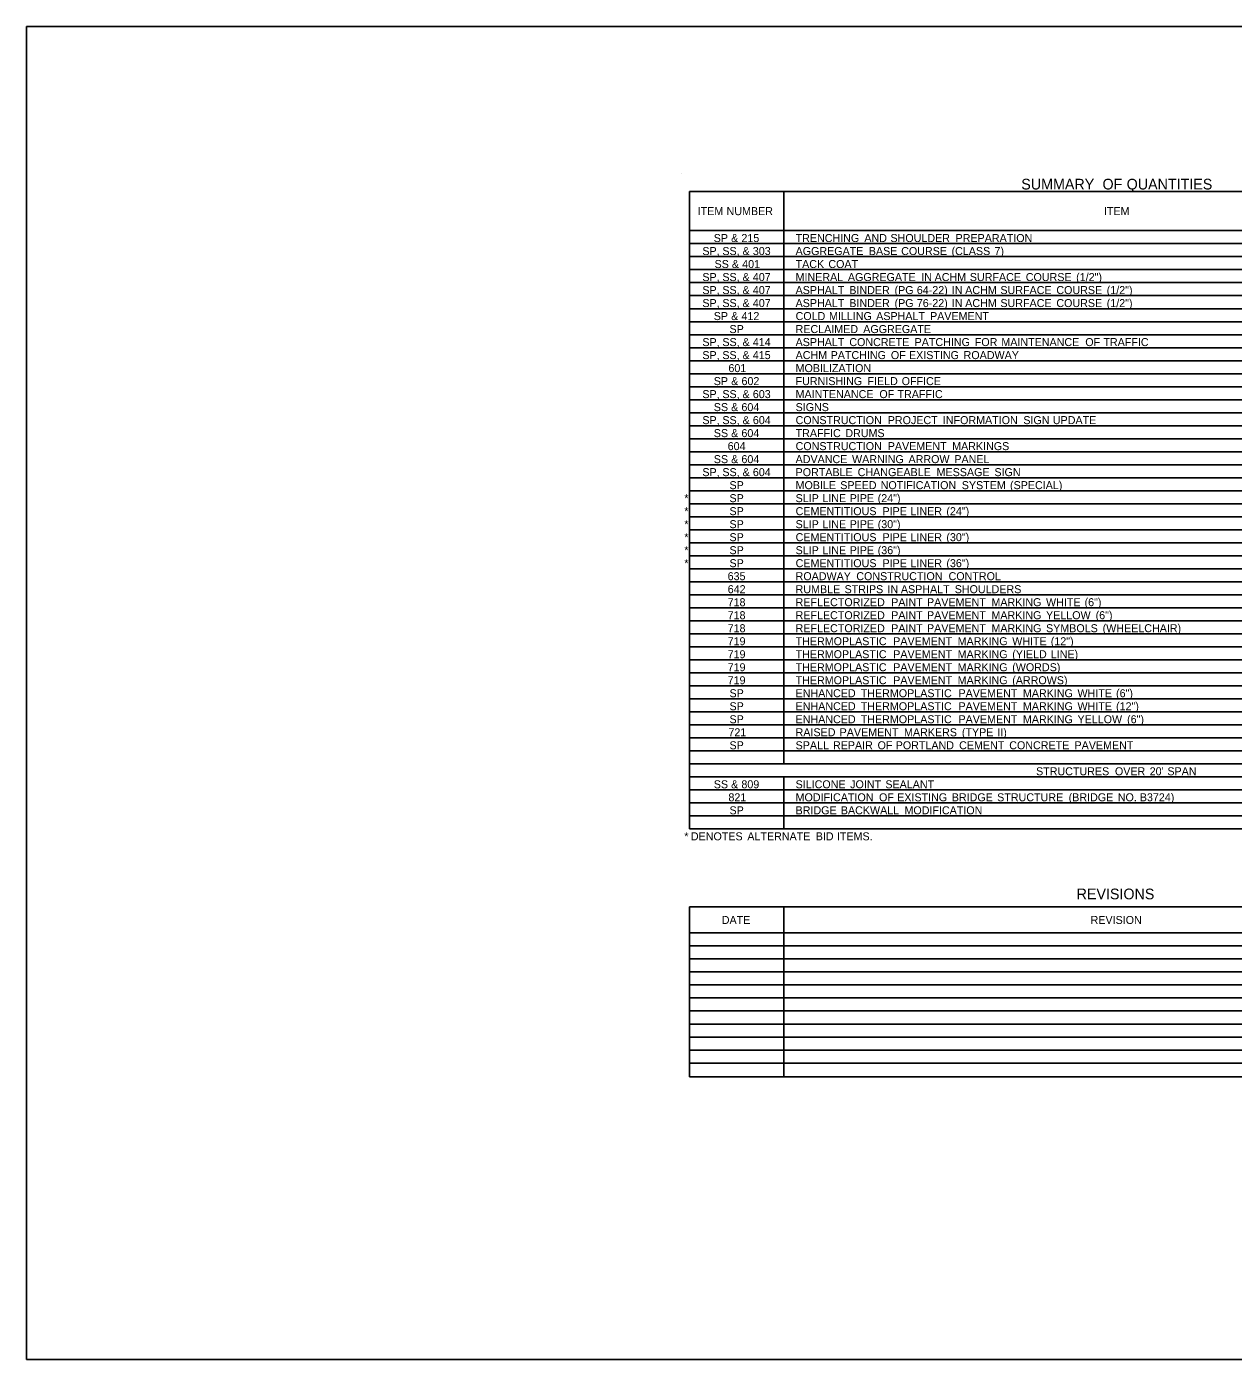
# Model space of a CAD drawing. Extents: x 2261867 to 2275370, y -3124789 to -3122260.
# Drawn here: x 2273745 to 2274649, y -3124789 to -3123790 of the extents above; entities that cross this region are included whole.
import ezdxf

# ---------------------------------------------------------------- set-up
doc = ezdxf.new("R2010")
doc.units = 0
for name, color, linetype in [('Default', 7, 'Continuous'), ('DSN_DRFT_DNC', 7, 'Continuous'), ('DSN_DRFT_Named-Boundary', 7, 'Continuous')]:
    doc.layers.add(name, color=color, linetype=linetype)

msp = doc.modelspace()

# ---------------------------------------------------------------- linework, layer by layer
at = {"layer": 'Default'}
for p, q in [((2274241.54, -3123913.99), (2274312.22, -3123913.99)), ((2274241.54, -3123913.99), (2274910.87, -3123913.99)), ((2274241.54, -3124391.74), (2274241.54, -3123913.99)), ((2274241.54, -3124391.74), (2274241.54, -3123913.99)), ((2274312.22, -3124342.99), (2274312.22, -3123913.99)), ((2274241.54, -3123943.24), (2274910.87, -3123943.24)), ((2274241.54, -3123943.24), (2274910.87, -3123943.24)), ((2274312.22, -3124342.99), (2274312.22, -3123943.24)), ((2274241.54, -3123952.99), (2274910.87, -3123952.99)), ((2274241.54, -3123962.74), (2274910.87, -3123962.74)), ((2274241.54, -3123972.49), (2274910.87, -3123972.49)), ((2274241.54, -3123982.24), (2274910.87, -3123982.24)), ((2274241.54, -3123991.99), (2274910.87, -3123991.99)), ((2274241.54, -3124001.74), (2274910.87, -3124001.74)), ((2274241.54, -3124011.49), (2274910.87, -3124011.49)), ((2274241.54, -3124021.24), (2274910.87, -3124021.24)), ((2274241.54, -3124030.99), (2274910.87, -3124030.99)), ((2274241.54, -3124040.74), (2274910.87, -3124040.74)), ((2274241.54, -3124050.49), (2274910.87, -3124050.49)), ((2274241.54, -3124060.24), (2274910.87, -3124060.24)), ((2274241.54, -3124069.99), (2274910.87, -3124069.99)), ((2274241.54, -3124079.74), (2274910.87, -3124079.74)), ((2274241.54, -3124089.49), (2274910.87, -3124089.49)), ((2274241.54, -3124099.24), (2274910.87, -3124099.24)), ((2274241.54, -3124108.99), (2274910.87, -3124108.99)), ((2274241.54, -3124118.74), (2274910.87, -3124118.74)), ((2274241.54, -3124128.49), (2274910.87, -3124128.49)), ((2274241.54, -3124138.24), (2274910.87, -3124138.24)), ((2274241.54, -3124147.99), (2274910.87, -3124147.99)), ((2274241.54, -3124157.74), (2274910.87, -3124157.74)), ((2274241.54, -3124167.49), (2274910.87, -3124167.49)), ((2274241.54, -3124177.24), (2274910.87, -3124177.24)), ((2274241.54, -3124186.99), (2274910.87, -3124186.99)), ((2274241.54, -3124196.74), (2274910.87, -3124196.74)), ((2274241.54, -3124206.49), (2274910.87, -3124206.49)), ((2274241.54, -3124216.24), (2274910.87, -3124216.24)), ((2274241.54, -3124225.99), (2274910.87, -3124225.99)), ((2274241.54, -3124235.74), (2274910.87, -3124235.74)), ((2274241.54, -3124245.49), (2274910.87, -3124245.49)), ((2274241.54, -3124255.24), (2274910.87, -3124255.24)), ((2274241.54, -3124264.99), (2274910.87, -3124264.99)), ((2274241.54, -3124274.74), (2274910.87, -3124274.74)), ((2274241.54, -3124284.49), (2274910.87, -3124284.49)), ((2274241.54, -3124294.24), (2274910.87, -3124294.24)), ((2274241.54, -3124303.99), (2274910.87, -3124303.99)), ((2274241.54, -3124313.74), (2274910.87, -3124313.74)), ((2274241.54, -3124323.49), (2274910.87, -3124323.49)), ((2274241.54, -3124333.24), (2274910.87, -3124333.24)), ((2274241.54, -3124342.99), (2274910.87, -3124342.99)), ((2274241.54, -3124352.74), (2274910.87, -3124352.74)), ((2274241.54, -3124352.74), (2274910.87, -3124352.74)), ((2274312.22, -3124391.74), (2274312.22, -3124352.74)), ((2274312.22, -3124391.74), (2274312.22, -3124352.74)), ((2274241.54, -3124362.49), (2274910.87, -3124362.49)), ((2274241.54, -3124372.24), (2274910.87, -3124372.24)), ((2274241.54, -3124381.99), (2274910.87, -3124381.99)), ((2274241.54, -3124391.74), (2274910.87, -3124391.74)), ((2274241.54, -3124450.24), (2274910.87, -3124450.24)), ((2274241.54, -3124450.24), (2274312.22, -3124450.24)), ((2274241.54, -3124577.48), (2274241.54, -3124450.24)), ((2274241.54, -3124577.48), (2274241.54, -3124450.24)), ((2274312.22, -3124577.48), (2274312.22, -3124450.24)), ((2274241.54, -3124469.74), (2274910.87, -3124469.74)), ((2274241.54, -3124479.49), (2274910.87, -3124479.49)), ((2274241.54, -3124489.24), (2274910.87, -3124489.24)), ((2274241.54, -3124498.99), (2274910.87, -3124498.99)), ((2274241.54, -3124508.74), (2274910.87, -3124508.74)), ((2274241.54, -3124518.49), (2274910.87, -3124518.49)), ((2274241.54, -3124528.24), (2274910.87, -3124528.24)), ((2274241.54, -3124537.99), (2274910.87, -3124537.99)), ((2274241.54, -3124547.74), (2274910.87, -3124547.74)), ((2274241.54, -3124557.49), (2274910.87, -3124557.49)), ((2274241.54, -3124567.24), (2274910.87, -3124567.24)), ((2274241.54, -3124577.48), (2274910.87, -3124577.48))]:
    msp.add_line(p, q, dxfattribs=at)
at = {"layer": 'DSN_DRFT_DNC'}
msp.add_line((2274235.69, -3123900.34), (2274235.69, -3123900.34), dxfattribs=at)
at = {"layer": 'DSN_DRFT_Named-Boundary'}
msp.add_lwpolyline([(2273744.64, -3124789.38), (2275369.64, -3124789.38), (2275369.64, -3123790.32), (2273744.64, -3123790.32)], close=True, dxfattribs=at)

# ---------------------------------------------------------------- texts
at = {"layer": 'Default'}
for s, height, p in [(' SUMMARY', 8, (2274487.2, -3123912.39)), (' OF', 8, (2274548.08, -3123912.39)), (' QUANTITIES', 8, (2274566.19, -3123912.39)), ('ITEM', 6, (2274247.62, -3123931.62)), (' NUMBER', 6, (2274267.05, -3123931.62)), ('ITEM', 6, (2274552.11, -3123931.62)), ('SP', 6, (2274259.62, -3123951.79)), (' &', 6, (2274270.44, -3123951.79)), (' 215', 6, (2274278.17, -3123951.79)), ('TRENCHING', 6, (2274321, -3123951.79)), (' AND', 6, (2274370.31, -3123951.79)), (' SHOULDER', 6, (2274389.89, -3123951.79)), (' PREPARATION', 6, (2274438.69, -3123951.79)), ('SP,', 6, (2274251.12, -3123961.54)), (' SS,', 6, (2274263.89, -3123961.54)), (' &', 6, (2274278.98, -3123961.54)), (' 303', 6, (2274286.71, -3123961.54)), ('AGGREGATE', 6, (2274321, -3123961.54)), (' BASE', 6, (2274373.66, -3123961.54)), (' COURSE', 6, (2274397.91, -3123961.54)), (' (CLASS', 6, (2274435.67, -3123961.54)), (' 7)', 6, (2274467.84, -3123961.54)), ('SS', 6, (2274260.26, -3123971.29)), (' &', 6, (2274271.01, -3123971.29)), (' 401', 6, (2274278.73, -3123971.29)), ('TACK', 6, (2274321, -3123971.29)), (' COAT', 6, (2274343.34, -3123971.29)), ('SP,', 6, (2274251.12, -3123981.04)), (' SS,', 6, (2274263.89, -3123981.04)), (' &', 6, (2274278.98, -3123981.04)), (' 407', 6, (2274286.71, -3123981.04)), ('MINERAL', 6, (2274321, -3123981.04)), (' AGGREGATE', 6, (2274357.97, -3123981.04)), (' IN', 6, (2274412.96, -3123981.04)), (' ACHM', 6, (2274422.98, -3123981.04)), (' SURFACE', 6, (2274449.37, -3123981.04)), (' COURSE', 6, (2274491.31, -3123981.04)), (' (1/2")', 6, (2274529.06, -3123981.04)), ('SP,', 6, (2274251.12, -3123990.79)), (' SS,', 6, (2274263.89, -3123990.79)), (' &', 6, (2274278.98, -3123990.79)), (' 407', 6, (2274286.71, -3123990.79)), ('ASPHALT', 6, (2274321, -3123990.79)), (' BINDER', 6, (2274359.04, -3123990.79)), (' (PG', 6, (2274392.93, -3123990.79)), (' 64-22)', 6, (2274409.64, -3123990.79)), (' IN', 6, (2274435.88, -3123990.79)), (' ACHM', 6, (2274445.91, -3123990.79)), (' SURFACE', 6, (2274472.29, -3123990.79)), (' COURSE', 6, (2274514.23, -3123990.79)), (' (1/2")', 6, (2274551.98, -3123990.79)), ('SP,', 6, (2274251.12, -3124000.54)), (' SS,', 6, (2274263.89, -3124000.54)), (' &', 6, (2274278.98, -3124000.54)), (' 407', 6, (2274286.71, -3124000.54)), ('ASPHALT', 6, (2274321, -3124000.54)), (' BINDER', 6, (2274359.04, -3124000.54)), (' (PG', 6, (2274392.93, -3124000.54)), (' 76-22)', 6, (2274409.64, -3124000.54)), (' IN', 6, (2274435.88, -3124000.54)), (' ACHM', 6, (2274445.91, -3124000.54)), (' SURFACE', 6, (2274472.29, -3124000.54)), (' COURSE', 6, (2274514.23, -3124000.54)), (' (1/2")', 6, (2274551.98, -3124000.54)), ('SP', 6, (2274259.67, -3124010.29)), (' &', 6, (2274270.49, -3124010.29)), (' 412', 6, (2274278.22, -3124010.29)), ('COLD', 6, (2274321, -3124010.29)), (' MILLING', 6, (2274343.84, -3124010.29)), (' ASPHALT', 6, (2274379.18, -3124010.29)), (' PAVEMENT', 6, (2274419.55, -3124010.29)), ('SP', 6, (2274271.47, -3124020.04)), ('RECLAIMED', 6, (2274321, -3124020.04)), (' AGGREGATE', 6, (2274369.46, -3124020.04)), ('SP,', 6, (2274251.13, -3124029.79)), (' SS,', 6, (2274263.9, -3124029.79)), (' &', 6, (2274279, -3124029.79)), (' 414', 6, (2274286.73, -3124029.79)), ('ASPHALT', 6, (2274321, -3124029.79)), (' CONCRETE', 6, (2274359.04, -3124029.79)), (' PATCHING', 6, (2274407.97, -3124029.79)), (' FOR', 6, (2274453.09, -3124029.79)), (' MAINTENANCE', 6, (2274473, -3124029.79)), (' OF', 6, (2274535.91, -3124029.79)), (' TRAFFIC', 6, (2274549.49, -3124029.79)), ('SP,', 6, (2274251.1, -3124039.54)), (' SS,', 6, (2274263.86, -3124039.54)), (' &', 6, (2274278.96, -3124039.54)), (' 415', 6, (2274286.69, -3124039.54)), ('ACHM', 6, (2274321, -3124039.54)), (' PATCHING', 6, (2274345.05, -3124039.54)), (' OF', 6, (2274390.18, -3124039.54)), (' EXISTING', 6, (2274403.76, -3124039.54)), (' ROADWAY', 6, (2274444.7, -3124039.54)), ('601', 6, (2274270.66, -3124049.29)), ('MOBILIZATION', 6, (2274321, -3124049.29)), ('SP', 6, (2274259.67, -3124059.04)), (' &', 6, (2274270.49, -3124059.04)), (' 602', 6, (2274278.22, -3124059.04)), ('FURNISHING', 6, (2274321, -3124059.04)), (' FIELD', 6, (2274372.64, -3124059.04)), (' OFFICE', 6, (2274398.28, -3124059.04)), ('SP,', 6, (2274251.12, -3124068.79)), (' SS,', 6, (2274263.89, -3124068.79)), (' &', 6, (2274278.98, -3124068.79)), (' 603', 6, (2274286.71, -3124068.79)), ('MAINTENANCE', 6, (2274321, -3124068.79)), (' OF', 6, (2274381.57, -3124068.79)), (' TRAFFIC', 6, (2274395.16, -3124068.79)), ('SS', 6, (2274259.69, -3124078.54)), (' &', 6, (2274270.44, -3124078.54)), (' 604', 6, (2274278.17, -3124078.54)), ('SIGNS', 6, (2274321, -3124078.54)), ('SP,', 6, (2274251.13, -3124088.29)), ('SS', 6, (2274259.69, -3124098.04)), (' SS,', 6, (2274263.9, -3124088.29)), (' &', 6, (2274270.44, -3124098.04)), (' 604', 6, (2274278.17, -3124098.04)), (' &', 6, (2274279, -3124088.29)), (' 604', 6, (2274286.73, -3124088.29)), ('TRAFFIC', 6, (2274321, -3124098.04)), ('CONSTRUCTION', 6, (2274321, -3124088.29)), (' DRUMS', 6, (2274356.06, -3124098.04)), (' PROJECT', 6, (2274387.85, -3124088.29)), (' INFORMATION', 6, (2274429.14, -3124088.29)), (' SIGN', 6, (2274489.46, -3124088.29)), (' UPDATE', 6, (2274511.6, -3124088.29)), ('604', 6, (2274270.09, -3124107.79)), ('CONSTRUCTION', 6, (2274321, -3124107.79)), (' PAVEMENT', 6, (2274387.85, -3124107.79)), (' MARKINGS', 6, (2274436.13, -3124107.79)), ('SS', 6, (2274259.69, -3124117.54)), (' &', 6, (2274270.44, -3124117.54)), (' 604', 6, (2274278.17, -3124117.54)), ('ADVANCE', 6, (2274321, -3124117.54)), (' WARNING', 6, (2274361.09, -3124117.54)), (' ARROW', 6, (2274403.41, -3124117.54)), (' PANEL', 6, (2274437.77, -3124117.54)), ('SP,', 6, (2274251.13, -3124127.29)), (' SS,', 6, (2274263.9, -3124127.29)), (' &', 6, (2274279, -3124127.29)), (' 604', 6, (2274286.73, -3124127.29)), ('PORTABLE', 6, (2274321, -3124127.29)), (' CHANGEABLE', 6, (2274365.28, -3124127.29)), (' MESSAGE', 6, (2274424.47, -3124127.29)), (' SIGN', 6, (2274467.82, -3124127.29)), ('SP', 6, (2274271.47, -3124137.04)), ('MOBILE', 6, (2274321, -3124137.04)), (' SPEED', 6, (2274352.23, -3124137.04)), (' NOTIFICATION', 6, (2274382.53, -3124137.04)), (' SYSTEM', 6, (2274443.33, -3124137.04)), (' (SPECIAL)', 6, (2274479.5, -3124137.04)), ('*', 6, (2274237.59, -3124146.79)), ('SP', 6, (2274271.47, -3124146.79)), ('SLIP', 6, (2274321, -3124146.79)), (' LINE', 6, (2274338.81, -3124146.79)), (' PIPE', 6, (2274359.32, -3124146.79)), (' (24")', 6, (2274380.31, -3124146.79)), ('*', 6, (2274237.59, -3124156.54)), ('SP', 6, (2274271.47, -3124156.54)), ('CEMENTITIOUS', 6, (2274321, -3124156.54)), (' PIPE', 6, (2274383.91, -3124156.54)), (' LINER', 6, (2274404.89, -3124156.54)), (' (24")', 6, (2274431.8, -3124156.54)), ('*', 6, (2274237.59, -3124166.29)), ('SP', 6, (2274271.47, -3124166.29)), ('SLIP', 6, (2274321, -3124166.29)), (' LINE', 6, (2274338.81, -3124166.29)), (' PIPE', 6, (2274359.32, -3124166.29)), (' (30")', 6, (2274380.31, -3124166.29)), ('*', 6, (2274237.59, -3124176.04)), ('SP', 6, (2274271.47, -3124176.04)), ('CEMENTITIOUS', 6, (2274321, -3124176.04)), (' PIPE', 6, (2274383.91, -3124176.04)), (' LINER', 6, (2274404.89, -3124176.04)), (' (30")', 6, (2274431.8, -3124176.04)), ('*', 6, (2274237.59, -3124185.79)), ('SP', 6, (2274271.47, -3124185.79)), ('SLIP', 6, (2274321, -3124185.79)), (' LINE', 6, (2274338.81, -3124185.79)), (' PIPE', 6, (2274359.32, -3124185.79)), (' (36")', 6, (2274380.31, -3124185.79)), ('*', 6, (2274237.59, -3124195.54)), ('SP', 6, (2274271.47, -3124195.54)), ('CEMENTITIOUS', 6, (2274321, -3124195.54)), (' PIPE', 6, (2274383.91, -3124195.54)), (' LINER', 6, (2274404.89, -3124195.54)), (' (36")', 6, (2274431.8, -3124195.54)), ('635', 6, (2274270.06, -3124205.29)), ('ROADWAY', 6, (2274321, -3124205.29)), (' CONSTRUCTION', 6, (2274364.26, -3124205.29)), (' CONTROL', 6, (2274433.43, -3124205.29)), ('642', 6, (2274270.11, -3124215.04)), ('RUMBLE', 6, (2274321, -3124215.04)), (' STRIPS', 6, (2274355.49, -3124215.04)), (' IN', 6, (2274387.66, -3124215.04)), (' ASPHALT', 6, (2274397.69, -3124215.04)), (' SHOULDERS', 6, (2274438.05, -3124215.04)), ('718', 6, (2274270.07, -3124224.79)), ('REFLECTORIZED', 6, (2274321, -3124224.79)), (' PAINT', 6, (2274390.42, -3124224.79)), (' PAVEMENT', 6, (2274417.27, -3124224.79)), (' MARKING', 6, (2274465.56, -3124224.79)), (' WHITE', 6, (2274506.49, -3124224.79)), (' (6")', 6, (2274535.37, -3124224.79)), ('718', 6, (2274270.07, -3124234.54)), ('REFLECTORIZED', 6, (2274321, -3124234.54)), (' PAINT', 6, (2274390.42, -3124234.54)), (' PAVEMENT', 6, (2274417.27, -3124234.54)), (' MARKING', 6, (2274465.56, -3124234.54)), (' YELLOW', 6, (2274506.49, -3124234.54)), (' (6")', 6, (2274543.66, -3124234.54)), ('718', 6, (2274270.07, -3124244.29)), ('REFLECTORIZED', 6, (2274321, -3124244.29)), (' PAINT', 6, (2274390.42, -3124244.29)), (' PAVEMENT', 6, (2274417.27, -3124244.29)), (' MARKING', 6, (2274465.56, -3124244.29)), (' SYMBOLS', 6, (2274506.49, -3124244.29)), (' (WHEELCHAIR)', 6, (2274548.91, -3124244.29)), ('719', 6, (2274270.07, -3124254.04)), ('THERMOPLASTIC', 6, (2274321, -3124254.04)), (' PAVEMENT', 6, (2274391.94, -3124254.04)), (' MARKING', 6, (2274440.22, -3124254.04)), (' WHITE', 6, (2274481.15, -3124254.04)), (' (12")', 6, (2274510.04, -3124254.04)), ('719', 6, (2274270.07, -3124263.79)), ('THERMOPLASTIC', 6, (2274321, -3124263.79)), (' PAVEMENT', 6, (2274391.94, -3124263.79)), (' MARKING', 6, (2274440.22, -3124263.79)), (' (YIELD', 6, (2274481.15, -3124263.79)), (' LINE)', 6, (2274510.05, -3124263.79)), ('719', 6, (2274270.07, -3124273.54)), ('THERMOPLASTIC', 6, (2274321, -3124273.54)), (' PAVEMENT', 6, (2274391.94, -3124273.54)), (' MARKING', 6, (2274440.22, -3124273.54)), (' (WORDS)', 6, (2274481.15, -3124273.54)), ('719', 6, (2274270.07, -3124283.29)), ('THERMOPLASTIC', 6, (2274321, -3124283.29)), (' PAVEMENT', 6, (2274391.94, -3124283.29)), (' MARKING', 6, (2274440.22, -3124283.29)), (' (ARROWS)', 6, (2274481.15, -3124283.29)), ('SP', 6, (2274271.47, -3124293.04)), ('ENHANCED', 6, (2274321, -3124293.04)), (' THERMOPLASTIC', 6, (2274367.6, -3124293.04)), (' PAVEMENT', 6, (2274440.87, -3124293.04)), (' MARKING', 6, (2274489.15, -3124293.04)), (' WHITE', 6, (2274530.08, -3124293.04)), (' (6")', 6, (2274558.97, -3124293.04)), ('SP', 6, (2274271.47, -3124302.79)), ('ENHANCED', 6, (2274321, -3124302.79)), (' THERMOPLASTIC', 6, (2274367.6, -3124302.79)), (' PAVEMENT', 6, (2274440.87, -3124302.79)), (' MARKING', 6, (2274489.15, -3124302.79)), (' WHITE', 6, (2274530.08, -3124302.79)), (' (12")', 6, (2274558.97, -3124302.79)), ('SP', 6, (2274271.47, -3124312.54)), ('ENHANCED', 6, (2274321, -3124312.54)), (' THERMOPLASTIC', 6, (2274367.6, -3124312.54)), (' PAVEMENT', 6, (2274440.87, -3124312.54)), (' MARKING', 6, (2274489.15, -3124312.54)), (' YELLOW', 6, (2274530.08, -3124312.54)), (' (6")', 6, (2274567.25, -3124312.54)), ('721', 6, (2274270.66, -3124322.29)), ('RAISED', 6, (2274321, -3124322.29)), (' PAVEMENT', 6, (2274351.77, -3124322.29)), (' MARKERS', 6, (2274400.05, -3124322.29)), (' (TYPE', 6, (2274443.4, -3124322.29)), (' II)', 6, (2274469.97, -3124322.29)), ('SP', 6, (2274271.47, -3124332.04)), ('SPALL', 6, (2274321, -3124332.04)), (' REPAIR', 6, (2274346.8, -3124332.04)), (' OF', 6, (2274380.23, -3124332.04)), (' PORTLAND', 6, (2274393.82, -3124332.04)), (' CEMENT', 6, (2274441.35, -3124332.04)), (' CONCRETE', 6, (2274478.91, -3124332.04)), (' PAVEMENT', 6, (2274527.84, -3124332.04)), ('STRUCTURES', 6, (2274501.24, -3124351.54)), (' OVER', 6, (2274558.13, -3124351.54)), (" 20'", 6, (2274584.18, -3124351.54)), (' SPAN', 6, (2274597.45, -3124351.54)), ('SS', 6, (2274259.67, -3124361.29)), (' &', 6, (2274270.42, -3124361.29)), (' 809', 6, (2274278.15, -3124361.29)), ('SILICONE', 6, (2274321, -3124361.29)), (' JOINT', 6, (2274359.68, -3124361.29)), (' SEALANT', 6, (2274386.06, -3124361.29)), ('821', 6, (2274270.66, -3124371.04)), ('MODIFICATION', 6, (2274321, -3124371.04)), (' OF', 6, (2274381.32, -3124371.04)), (' EXISTING', 6, (2274394.91, -3124371.04)), (' BRIDGE', 6, (2274435.84, -3124371.04)), (' STRUCTURE', 6, (2274469.87, -3124371.04)), (' (BRIDGE', 6, (2274523.45, -3124371.04)), (' NO.', 6, (2274560.27, -3124371.04)), (' B3724)', 6, (2274576.77, -3124371.04)), ('SP', 6, (2274271.47, -3124380.79)), ('BRIDGE', 6, (2274321, -3124380.79)), (' BACKWALL', 6, (2274352.69, -3124380.79)), (' MODIFICATION', 6, (2274400.38, -3124380.79)), ('*', 6, (2274237.59, -3124400.29)), ('DENOTES', 6, (2274242.51, -3124400.29)), (' ALTERNATE', 6, (2274282.6, -3124400.29)), (' BID', 6, (2274333.87, -3124400.29)), (' ITEMS.', 6, (2274349.72, -3124400.29)), ('REVISIONS', 8, (2274531.66, -3124444.49)), ('DATE', 6, (2274265.68, -3124462.99)), ('REVISION', 6, (2274542.13, -3124462.99))]:
    msp.add_text(s, height=height, dxfattribs=at).set_placement(p)

doc.saveas('drawing.dxf')
